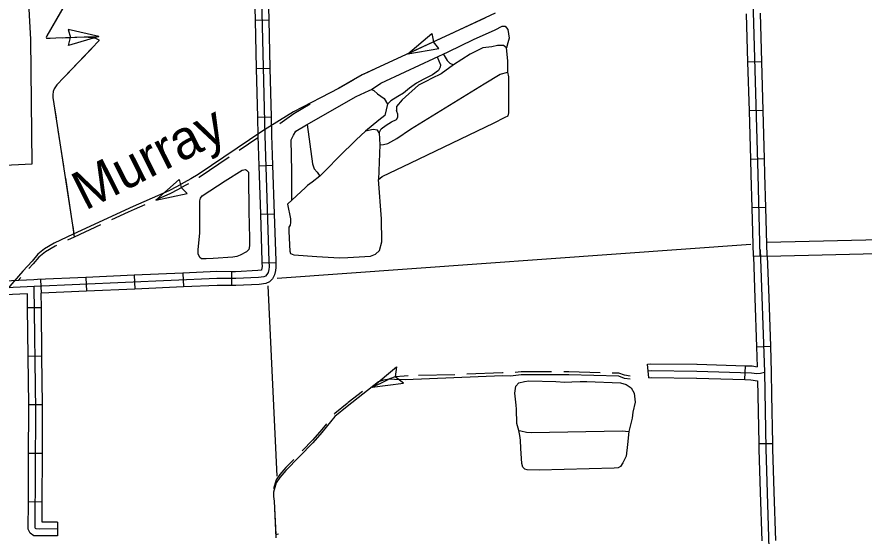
# Model space of a CAD drawing. Extents: x 1164457 to 1439835, y 1590918 to 1773502.
# Drawn here: x 1258762 to 1267982, y 1620143 to 1625786 of the extents above; entities that cross this region are included whole.
import ezdxf

# ---------------------------------------------------------------- set-up
doc = ezdxf.new("R2010")
doc.units = 0
for name, color, linetype in [('Level 32', 7, 'Continuous'), ('Level 35', 7, 'Continuous'), ('Level 43', 7, 'Continuous'), ('Level 45', 7, 'Continuous'), ('Level 46', 7, 'Continuous'), ('Level 5', 7, 'Continuous'), ('Level 6', 7, 'Continuous')]:
    doc.layers.add(name, color=color, linetype=linetype)

msp = doc.modelspace()

# ---------------------------------------------------------------- linework, layer by layer
at = {"layer": 'Level 32'}
for p, q in [((1261353.4, 1625752.4), (1261503.4, 1625756)), ((1266868.8, 1625297.7), (1266718.9, 1625293.5)), ((1261366.2, 1625224.6), (1261516.1, 1625228.2)), ((1266883.6, 1624769.9), (1266733.7, 1624765.7)), ((1261378.9, 1624696.7), (1261528.9, 1624700.3)), ((1261394.4, 1624168.3), (1261544.3, 1624173.2)), ((1266898.4, 1624242.1), (1266748.5, 1624237.9)), ((1266913, 1623714.3), (1266763.1, 1623710.2)), ((1261411.5, 1623640.6), (1261561.4, 1623645.5)), ((1266927.6, 1623186.5), (1266777.6, 1623182.4)), ((1261428.7, 1623112.4), (1261578.6, 1623118.3)), ((1260039, 1622977.4), (1260045.6, 1622827.6)), ((1260566.5, 1623000.7), (1260573, 1622850.8)), ((1261097.7, 1623016.3), (1261097.1, 1622866.3)), ((1259019.3, 1622932.6), (1259025.9, 1622782.7)), ((1259511.5, 1622954.2), (1259518.1, 1622804.4)), ((1259027.7, 1622625.5), (1258877.8, 1622623.8)), ((1259033.9, 1622097.6), (1258883.9, 1622095.8)), ((1259040, 1621569.6), (1258890, 1621567.8)), ((1259039, 1621040.4), (1258889, 1621041)), ((1259037, 1620512.4), (1258887, 1620513)), ((1259201.8, 1620295.1), (1259202.8, 1620145.1))]:
    msp.add_line(p, q, dxfattribs=at)
for points in [[(1261295.4, 1630547.9), (1261306.2, 1630051), (1261324.9, 1629664.4), (1261348.7, 1628964), (1261365.2, 1628368), (1261458.8, 1624497.4), (1261503, 1623132.1), (1261505.5, 1623067.7), (1261501.7, 1623041.2), (1261495.4, 1623009.6), (1261481.5, 1622985.6), (1261466, 1622969.5), (1261449.4, 1622961.7), (1261391.9, 1622953.3), (1261142.6, 1622941.1), (1260938.5, 1622942), (1258950.1, 1622854.5), (1257949.9, 1622809.2), (1257180.1, 1622788.2), (1256671, 1622766), (1256306.3, 1622746.2), (1255487.8, 1622688.9), (1251482.4, 1622430.4), (1250992.3, 1622408.6)], [(1266852.6, 1623184.4), (1266828.1, 1624073.7), (1266703.8, 1628503.4)], [(1261490.6, 1626283.9), (1261503.4, 1625756)], [(1261340.7, 1626280.3), (1261353.4, 1625752.4)], [(1266718.9, 1625293.5), (1266704, 1625821.3)], [(1266868.8, 1625297.7), (1266854, 1625825.5)], [(1261353.4, 1625752.4), (1261366.2, 1625224.6)], [(1261503.4, 1625756), (1261516.1, 1625228.2)], [(1266733.7, 1624765.7), (1266718.9, 1625293.5)], [(1266883.6, 1624769.9), (1266868.8, 1625297.7)], [(1261366.2, 1625224.6), (1261378.9, 1624696.7)], [(1261516.1, 1625228.2), (1261528.9, 1624700.3)], [(1266748.5, 1624237.9), (1266733.7, 1624765.7)], [(1266898.4, 1624242.1), (1266883.6, 1624769.9)], [(1261378.9, 1624696.7), (1261383.8, 1624495.3), (1261394.4, 1624168.3)], [(1261528.9, 1624700.3), (1261533.7, 1624499.6), (1261544.3, 1624173.2)], [(1261394.4, 1624168.3), (1261411.5, 1623640.6)], [(1261544.3, 1624173.2), (1261561.4, 1623645.5)], [(1266763.1, 1623710.2), (1266753.1, 1624071.7), (1266748.5, 1624237.9)], [(1266913, 1623714.3), (1266903.1, 1624075.8), (1266898.4, 1624242.1)], [(1266777.6, 1623182.4), (1266763.1, 1623710.2)], [(1266927.6, 1623186.5), (1266913, 1623714.3)], [(1261411.5, 1623640.6), (1261428, 1623129.4), (1261428.7, 1623112.4)], [(1261561.4, 1623645.5), (1261577.9, 1623134.8), (1261578.6, 1623118.3)], [(1261578.6, 1623118.3), (1261580.7, 1623063.8), (1261575.7, 1623028.5), (1261566.5, 1622982.7), (1261541.9, 1622940.2), (1261510.4, 1622907.4), (1261471.1, 1622889.1), (1261399.2, 1622878.6), (1261144.2, 1622866.1), (1261097.1, 1622866.3)], [(1261428.7, 1623112.4), (1261430.3, 1623071.6), (1261427.8, 1623053.8), (1261424.3, 1623036.4), (1261422.6, 1623033.6), (1261384.7, 1623028), (1261140.9, 1623016.2), (1261097.7, 1623016.3)], [(1260039, 1622977.4), (1259511.5, 1622954.2)], [(1260566.5, 1623000.7), (1260039, 1622977.4)], [(1261097.7, 1623016.3), (1260937, 1623017), (1260566.5, 1623000.7)], [(1258984, 1622931), (1258946.7, 1622929.4), (1258456.4, 1622907.2)], [(1259511.5, 1622954.2), (1258984, 1622931)], [(1259202.3, 1620220.1), (1259004.9, 1620218.7), (1258970.8, 1620220.1), (1258965.1, 1620224.2), (1258960.9, 1620233.8), (1258965.7, 1621508.5), (1258950.1, 1622854.5)], [(1259518.1, 1622804.4), (1259025.9, 1622782.7)], [(1259027.7, 1622625.5), (1259025.9, 1622782.7)], [(1260045.6, 1622827.6), (1259518.1, 1622804.4)], [(1260573, 1622850.8), (1260045.6, 1622827.6)], [(1261097.1, 1622866.3), (1260940, 1622866.9), (1260573, 1622850.8)], [(1258876, 1622776), (1258463.2, 1622757.3)], [(1258877.8, 1622623.8), (1258876, 1622776)], [(1258883.9, 1622095.8), (1258877.8, 1622623.8)], [(1259033.9, 1622097.6), (1259027.7, 1622625.5)], [(1258890, 1621567.8), (1258883.9, 1622095.8)], [(1259040, 1621569.6), (1259033.9, 1622097.6)], [(1258889, 1621041), (1258890.7, 1621508.2), (1258890, 1621567.8)], [(1259039, 1621040.4), (1259040.7, 1621508.8), (1259040, 1621569.6)], [(1258887, 1620513), (1258889, 1621041)], [(1259037, 1620512.4), (1259039, 1621040.4)], [(1259202.8, 1620145.1), (1259003.6, 1620143.7), (1258945.7, 1620146), (1258904.6, 1620175.1), (1258885.8, 1620218.5), (1258887, 1620513)], [(1259201.8, 1620295.1), (1259036.1, 1620294), (1259037, 1620512.4)]]:
    msp.add_lwpolyline(points, dxfattribs=at)
at = {"layer": 'Level 35'}
for points in [[(1263454.6, 1625408.1), (1263731.5, 1625541.3), (1263966.4, 1625647.4), (1264042.2, 1625685.2), (1264075, 1625685.2), (1264105.3, 1625649.8), (1264120.5, 1625553.8), (1264105.3, 1625505.8), (1264088.8, 1625448.6)], [(1264116.6, 1624790), (1264114.1, 1625135.6), (1264106.5, 1625186.1), (1264106.5, 1625309.9), (1264088.8, 1625448.6), (1264058.5, 1625474.1), (1263992.8, 1625474.1), (1263929.7, 1625461.5), (1263831.2, 1625448.8), (1263694.8, 1625380.6), (1263513, 1625266.5), (1263378.5, 1625167.1), (1263272.9, 1625116.6)], [(1262619.4, 1624998), (1262722, 1625065.8), (1262987.1, 1625189.6), (1263454.6, 1625408.1)], [(1263402.3, 1625383.7), (1263443.5, 1625313.3), (1263473.8, 1625282.9), (1263513, 1625266.5)], [(1263335.2, 1625352.3), (1263371.6, 1625264), (1263369, 1625238.7), (1263352, 1625202.5), (1263285.1, 1625158.3), (1263182.8, 1625107.8)], [(1262709.9, 1624395.3), (1262752.8, 1624397.9), (1262798.3, 1624410.5), (1262896.8, 1624463.5), (1263045.8, 1624567.1), (1263848.9, 1625057.3), (1264023.1, 1625165.9), (1264106.5, 1625186.1)], [(1263182.8, 1625107.8), (1263110.8, 1625067.4), (1263035, 1625011.8), (1262967.5, 1624958.3), (1262906.9, 1624920.4), (1262831.1, 1624872.4), (1262794.2, 1624837.6)], [(1263272.9, 1625116.6), (1263218.1, 1625088.8), (1263131, 1625044.6), (1262953, 1624884.2), (1262891.7, 1624814.3), (1262894.2, 1624768.8)], [(1261912.3, 1624611.5), (1262455.3, 1624922.2), (1262596.7, 1624985.4), (1262619.4, 1624998), (1262647.2, 1624987.9), (1262687.6, 1624950), (1262759.2, 1624898.8), (1262794.2, 1624837.6)], [(1262794.2, 1624837.6), (1262766.5, 1624716.4), (1262702.3, 1624663.1), (1262555.8, 1624544), (1262453.3, 1624448.6), (1262266.4, 1624264.1), (1262130, 1624127.7), (1262059.3, 1624057), (1261976, 1623988.7), (1261923.6, 1623954.4)], [(1262728.6, 1623592.8), (1262695.7, 1624019.7), (1262736.2, 1624052.6), (1263048.3, 1624198.9), (1263949.9, 1624630.9), (1264076.2, 1624696.6), (1264109, 1624711.7), (1264116.6, 1624744.6), (1264116.6, 1624790)], [(1262704.8, 1624526.7), (1262727.6, 1624569.2), (1262780.6, 1624609.7), (1262838.7, 1624645), (1262894.2, 1624672.8), (1262906.9, 1624695.6), (1262906.9, 1624728.4), (1262896.8, 1624758.7), (1262894.2, 1624768.8)], [(1261755.4, 1623795.1), (1261753.5, 1624111), (1261748.4, 1624449.6), (1261771.2, 1624500.1), (1261796.4, 1624545.6), (1261912.3, 1624611.5)], [(1261921, 1624616.5), (1261978.5, 1624190.9), (1261996.2, 1624135.3), (1262029, 1624097.4), (1262059.3, 1624057)], [(1262704.8, 1624526.7), (1262687.2, 1624554.1), (1262639.2, 1624564.2), (1262555.8, 1624544)], [(1262704.8, 1624526.7), (1262709.9, 1624395.3), (1262695.7, 1624019.7)], [(1260754, 1623433.8), (1260754, 1623787.5), (1260759, 1623817.8), (1260776.7, 1623840.6), (1261029.3, 1624004.8), (1261213.6, 1624121), (1261249, 1624128.6), (1261259.1, 1624121), (1261281.8, 1624098.3), (1261281.8, 1624052.8), (1261286.9, 1623671.3)], [(1261923.6, 1623954.4), (1261902.6, 1623933.3), (1261707.5, 1623750.2)], [(1261707.5, 1623750.2), (1261741, 1623592.6), (1261740.3, 1623550.4), (1261734.7, 1623524.2), (1261720.8, 1623501.6), (1261720.8, 1623453.6), (1261733.4, 1623241.4), (1261738.5, 1623213.6), (1261776.3, 1623201), (1262026.4, 1623183.3), (1262271.1, 1623169)], [(1261286.9, 1623671.3), (1261291.9, 1623382.5), (1261291.9, 1623299.1), (1261286.9, 1623256.2), (1261259.1, 1623233.4), (1261190.9, 1623195.5), (1261155.5, 1623182.9), (1261110.1, 1623175.3), (1260897.9, 1623160.2), (1260822.2, 1623157.6), (1260769.1, 1623157.6), (1260751.5, 1623170.3), (1260733.8, 1623210.7), (1260733.8, 1623256.2), (1260754, 1623433.8)], [(1262271.1, 1623169), (1262364.9, 1623172.3), (1262609.9, 1623184.9), (1262662.9, 1623207.6), (1262708.4, 1623248.1), (1262733.6, 1623341.5), (1262728.6, 1623592.8)], [(1264194.7, 1621563.8), (1264181.9, 1621694.8), (1264192.9, 1621771.6), (1264223.1, 1621807.2), (1264286.1, 1621823.7), (1264332.7, 1621829.2), (1264628.7, 1621823.7), (1264724.7, 1621815.5), (1264801.4, 1621821), (1264891.9, 1621823.7), (1264965.9, 1621823.7), (1265330.5, 1621810), (1265393.5, 1621790.8), (1265445.6, 1621752.4), (1265481.2, 1621694.8), (1265492.2, 1621598.8), (1265466, 1621488.9)], [(1264223.2, 1621290.4), (1264204, 1621364.5), (1264198.5, 1621520.8), (1264194.7, 1621563.8)], [(1265466, 1621488.9), (1265456.7, 1621424.8), (1265421, 1621279.5)], [(1265421, 1621279.5), (1265407.3, 1621139.6), (1265393.6, 1621010.7), (1265358, 1620939.4), (1265330.6, 1620898.3), (1265305.9, 1620884.6), (1265262, 1620879.1), (1264445.2, 1620859.9), (1264316.4, 1620862.7), (1264291.7, 1620868.1), (1264269.8, 1620892.8), (1264256, 1620931.2), (1264247.8, 1621093), (1264242.3, 1621183.5), (1264236.9, 1621235.6), (1264223.2, 1621290.4)], [(1264223.2, 1621290.4), (1264247.8, 1621284.9), (1264308.1, 1621271.2), (1264363, 1621268.5), (1265349.8, 1621284.9), (1265421, 1621279.5)]]:
    msp.add_lwpolyline(points, dxfattribs=at)
at = {"layer": 'Level 43'}
for p, q in [((1259652.2, 1625575.4), (1259317.6, 1625651.5)), ((1259317.6, 1625651.5), (1259344.6, 1625564.3)), ((1259652.2, 1625575.4), (1259324.3, 1625474)), ((1259324.3, 1625474), (1259344.6, 1625563.1)), ((1263015.4, 1625386.1), (1263279.1, 1625605.8)), ((1263279.1, 1625605.8), (1263294.6, 1625515.8)), ((1263353.6, 1625444.6), (1263295.1, 1625514.7)), ((1263015.4, 1625386.1), (1263353.6, 1625444.6)), ((1260274.6, 1623795.7), (1260528.3, 1624020.5)), ((1260528.3, 1624020.5), (1260550.5, 1623931.9)), ((1260614.6, 1623865.2), (1260551.1, 1623930.8)), ((1260274.6, 1623795.7), (1260614.6, 1623865.2)), ((1262627.1, 1621762.8), (1262891.8, 1621981.3)), ((1262891.8, 1621981.3), (1262880.1, 1621873.2)), ((1262967.7, 1621804.6), (1262880.1, 1621873.2)), ((1262627.1, 1621762.8), (1262967.7, 1621804.6))]:
    msp.add_line(p, q, dxfattribs=at)
for points in [[(1259376.1, 1626084), (1259085.5, 1625581.3), (1259081.7, 1625562.3), (1259083.6, 1625553.7), (1259492.2, 1625569.3), (1259580.3, 1625563.3), (1259617.2, 1625556.6), (1259654.2, 1625535.7), (1259654.4, 1625525.2), (1259196.6, 1625046.6), (1259168.1, 1625005.8), (1259156.9, 1624977), (1259151.9, 1624941.2), (1259152.9, 1624910.8), (1259164.3, 1624841.5), (1259368, 1623524.1), (1259383.5, 1623393)], [(1263967.1, 1625827.1), (1263525.4, 1625621.9), (1262519.9, 1625156.9), (1262263.2, 1625008.9), (1261770.7, 1624753.8), (1261439.9, 1624549.1), (1260733.7, 1624072.8), (1260655.8, 1624025.9), (1260582.5, 1623987.3), (1260497.6, 1623940.2), (1260422.4, 1623900.5), (1260348.9, 1623866.9), (1260028.6, 1623726.7), (1259372.8, 1623425.4), (1259167.1, 1623327.2), (1259063.4, 1623264), (1258990.6, 1623205.7), (1258927.4, 1623132.8), (1258825.4, 1623023.6), (1258273.8, 1622390.2)], [(1259249, 1625864.2), (1259085.5, 1625581.3), (1259081.7, 1625562.3), (1259083.6, 1625553.7), (1259124.6, 1625555.3)], [(1263853.8, 1625774.5), (1263525.4, 1625621.9), (1263494.7, 1625607.7)], [(1259256.5, 1625560.3), (1259492.2, 1625569.3), (1259652.2, 1625575.4)], [(1263374.9, 1625552.3), (1263015.4, 1625386.1)], [(1259576.1, 1625443.3), (1259439.2, 1625300.2)], [(1259439.2, 1625300.2), (1259302.3, 1625157.2)], [(1262895.6, 1625330.7), (1262715.9, 1625247.6)], [(1262715.9, 1625247.6), (1262536.2, 1625164.5)], [(1262421.1, 1625100), (1262263.2, 1625008.9), (1262073.4, 1624910.6)], [(1259211.1, 1625061.8), (1259196.6, 1625046.6), (1259168.1, 1625005.8), (1259156.9, 1624977), (1259151.9, 1624941.2), (1259152.9, 1624910.8), (1259164.3, 1624841.5), (1259188.4, 1624685.8)], [(1261953.6, 1624839.6), (1261774.8, 1624731.6), (1261622.4, 1624623)], [(1259208.5, 1624555.3), (1259269, 1624164)], [(1261384.5, 1624472.2), (1261180.3, 1624334.4)], [(1261070.9, 1624260.6), (1260744.4, 1624040.4), (1260742.5, 1624039.3)], [(1259289.2, 1624033.5), (1259349.7, 1623642.2)], [(1260628.2, 1623973.4), (1260593.3, 1623955), (1260508.4, 1623907.8), (1260433.2, 1623868.1), (1260359.7, 1623834.6), (1260274, 1623797)], [(1260153.1, 1623744.1), (1260039.4, 1623694.4), (1259972.2, 1623663.5)], [(1259972.2, 1623663.5), (1259792.3, 1623580.8)], [(1259672.4, 1623525.7), (1259383.5, 1623393), (1259313, 1623359.4)], [(1259369.4, 1623511.7), (1259383.5, 1623393)], [(1259193.9, 1623302.5), (1259177.9, 1623294.8), (1259074.2, 1623231.6), (1259001.4, 1623173.3), (1258938.2, 1623100.4), (1258892.4, 1623051.4)], [(1258803.6, 1622953.8), (1258775.5, 1622921.6)], [(1265434.6, 1621847.1), (1265374.6, 1621857.1), (1265312.1, 1621879.6), (1264767.3, 1621894.6), (1264248.7, 1621894.6), (1264134.6, 1621879.3), (1264045.8, 1621884.3), (1262985.9, 1621840.6), (1262869.7, 1621844.3), (1262816, 1621849.3), (1262752.2, 1621835.6), (1262697.9, 1621818.1), (1262355.4, 1621550.8), (1262222.9, 1621442.1), (1262080.4, 1621269.5), (1261983, 1621154.5), (1261689.3, 1620855.8), (1261623.1, 1620779.5), (1261583.7, 1620720.7), (1261555.5, 1620621.5), (1261554.8, 1620572.2), (1261560, 1620523.2), (1261578.7, 1620124.4)], [(1263021.4, 1621885.9), (1262976.4, 1621882.5), (1262880.1, 1621873.2), (1262817.7, 1621852.3), (1262783.2, 1621835), (1262710.9, 1621797.9), (1262627.1, 1621762.8)], [(1263527.1, 1621896.3), (1263131, 1621889.1)], [(1264054.7, 1621917.2), (1264045.8, 1621917.7), (1263659, 1621901.7)], [(1264581.5, 1621927.9), (1264248.7, 1621927.9), (1264186.1, 1621919.6)], [(1265109.4, 1621918.5), (1264767.3, 1621927.9), (1264713.5, 1621927.9)], [(1265434.6, 1621880.4), (1265374.6, 1621890.4), (1265312.1, 1621912.9), (1265241.3, 1621914.9)], [(1262523, 1621715), (1262366.9, 1621593.2)], [(1262366.9, 1621593.2), (1262355.4, 1621584.2), (1262222.9, 1621475.4), (1262215.3, 1621466.2)], [(1262131.3, 1621364.4), (1262080.4, 1621302.8), (1261983, 1621187.8), (1261867, 1621069.9)], [(1261774.5, 1620975.8), (1261689.3, 1620889.2), (1261623.1, 1620812.9), (1261583.7, 1620754.1), (1261555.6, 1620655.2)], [(1261561.5, 1620523.6), (1261578.7, 1620157.8), (1261607.1, 1620166.9)]]:
    msp.add_lwpolyline(points, dxfattribs=at)
at = {"layer": 'Level 45'}
for p, q in [((1266812.5, 1622201.4), (1266962.4, 1622206.7)), ((1265639.6, 1621863.6), (1265625.4, 1622012.9)), ((1266685.9, 1621844.5), (1266690.3, 1621994.4)), ((1266835.4, 1621147.1), (1266985.4, 1621149.6))]:
    msp.add_line(p, q, dxfattribs=at)
for points in [[(1266850.5, 1623259.4), (1266897.3, 1621922.7), (1266911.4, 1621089.7), (1266968.8, 1619290.2), (1267006.2, 1617987.4), (1267004.3, 1617965.3)], [(1266777.6, 1623182.4), (1266794, 1622729.1)], [(1266927.6, 1623186.5), (1266944, 1622734.3)], [(1266794, 1622729.1), (1266812.5, 1622201.4)], [(1266944, 1622734.3), (1266962.4, 1622206.7)], [(1266812.5, 1622201.4), (1266820.1, 1621983.9)], [(1266962.4, 1622206.7), (1266972.3, 1621924.6), (1266976.5, 1621677.5)], [(1265625.4, 1622012.9), (1265660.6, 1622016.2), (1266161.2, 1622010)], [(1266161.2, 1622010), (1266164.5, 1622010), (1266690.3, 1621994.4)], [(1266690.3, 1621994.4), (1266765, 1621992.2), (1266820.1, 1621983.9)], [(1265632.5, 1621938.2), (1265663.7, 1621941.2), (1266163, 1621935), (1266758.2, 1621917.4), (1266816.3, 1621908.6), (1266855.1, 1621912.1), (1266870.9, 1621915.6), (1266897.3, 1621922.7)], [(1265639.6, 1621863.6), (1265666.8, 1621866.2), (1266159.4, 1621860.1)], [(1266159.4, 1621860.1), (1266161.4, 1621860), (1266685.9, 1621844.5)], [(1266685.9, 1621844.5), (1266751.5, 1621842.6), (1266823.9, 1621831.6)], [(1266823.9, 1621831.6), (1266826.5, 1621675)], [(1266826.5, 1621675), (1266835.4, 1621147.1)], [(1266976.5, 1621677.5), (1266985.4, 1621149.6)], [(1266835.4, 1621147.1), (1266836.4, 1621087.8), (1266851.4, 1620618.2)], [(1266985.4, 1621149.6), (1266986.4, 1621091.5), (1267001.3, 1620623)], [(1266851.4, 1620618.2), (1266868.2, 1620090.4)], [(1267001.3, 1620623), (1267018.2, 1620095.2)]]:
    msp.add_lwpolyline(points, dxfattribs=at)
at = {"layer": 'Level 46'}
for points in [[(1266923.4, 1623336.2), (1272156.8, 1623462.6)], [(1266927.6, 1623186.2), (1272160, 1623312.6)]]:
    msp.add_lwpolyline(points, dxfattribs=at)
at = {"layer": 'Level 5'}
for points in [[(1261592.9, 1622944.8), (1266748.2, 1623315)], [(1261492.2, 1622862), (1261588.9, 1620793.8)]]:
    msp.add_lwpolyline(points, dxfattribs=at)
at = {"layer": 'Level 6'}
msp.add_lwpolyline([(1256316.6, 1624060.7), (1258926.4, 1624190.1), (1258913.1, 1625540.6), (1258770.1, 1628119.8)], dxfattribs=at)

# ---------------------------------------------------------------- texts
at = {"layer": 'Level 43'}
msp.add_text('Murray', height=422, rotation=26.87296, dxfattribs=at).set_placement((1259504.7, 1623676.6))

doc.saveas('drawing.dxf')
